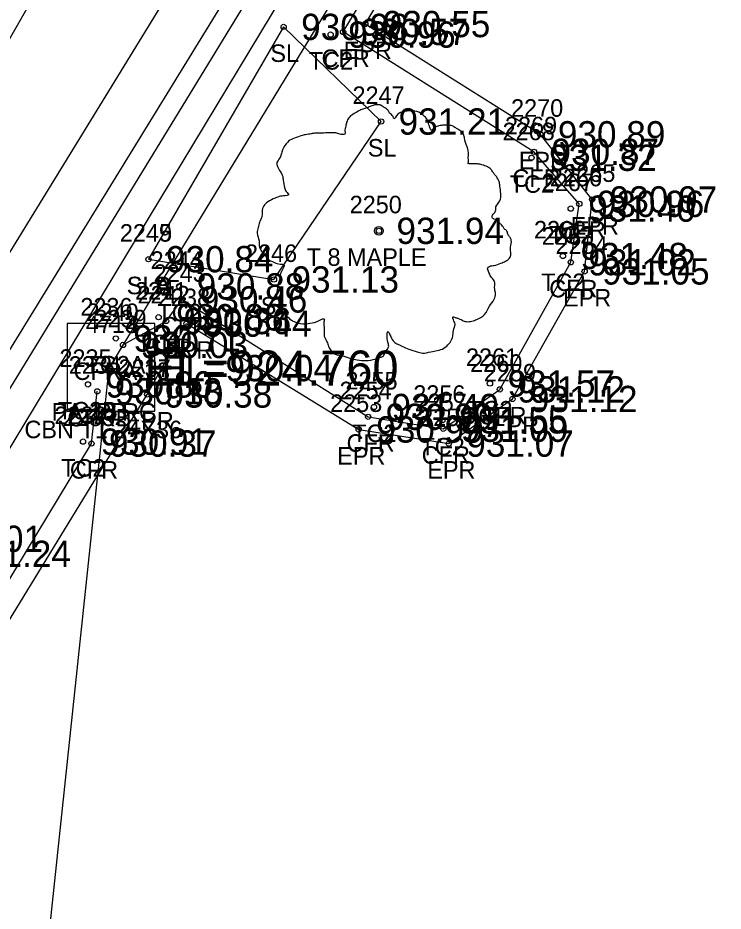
# Model space of a CAD drawing. Extents: x 1575382 to 1578175, y 1099175 to 1101955.
# Drawn here: x 1576685.7 to 1576726, y 1099948.9 to 1099999.9 of the extents above; entities that cross this region are included whole.
import ezdxf

# ---------------------------------------------------------------- set-up
doc = ezdxf.new("R2010")
doc.units = 0
for name, color, linetype in [('RD_EX_BldgApp', 7, 'Continuous'), ('RD_EX_Conc', 7, 'Continuous'), ('RD_EX_Conc_txCode', 7, 'Continuous'), ('RD_EX_DR_Inlet', 7, 'Continuous'), ('RD_EX_DR_Inlet_txCode', 7, 'Continuous'), ('RD_EX_DR_Pipe', 7, 'Continuous'), ('RD_EX_DR_Pipe_txCode', 7, 'Continuous'), ('RD_EX_Fence_Other', 7, 'Continuous'), ('RD_EX_Misc', 7, 'Continuous'), ('RD_EX_Road', 7, 'Continuous'), ('RD_EX_Road_txCode', 7, 'Continuous'), ('RD_EX_TX_Conc_ELEV', 7, 'Continuous'), ('RD_EX_TX_DR_Inlet_ELEV', 7, 'Continuous'), ('RD_EX_TX_Misc_ELEV', 7, 'Continuous'), ('RD_EX_TX_Road_ELEV', 7, 'Continuous'), ('RD_EX_TX_VEG_ELEV', 7, 'Continuous'), ('RD_EX_VEG', 7, 'Continuous'), ('RD_EX_VEG_txCode', 7, 'Continuous'), ('RD_SMD_Locator', 7, 'Continuous'), ('RD_TX_Pipe_ElevEX', 7, 'Continuous')]:
    doc.layers.add(name, color=color, linetype=linetype)

msp = doc.modelspace()

# ---------------------------------------------------------------- linework, layer by layer
at = {"layer": 'RD_EX_BldgApp'}
msp.add_lwpolyline([(1576672.285, 1099877.607), (1576646.299, 1099893.421), (1576642.266, 1099901.79), (1576647.555, 1099912.985), (1576656.827, 1099928.617), (1576681.633, 1099969.334), (1576707.301, 1100011.852), (1576732.079, 1100052.807), (1576750.28, 1100082.51)], dxfattribs=at)
at = {"layer": 'RD_EX_Conc'}
for points in [[(1576611.554, 1099868.428), (1576613.247, 1099872.406), (1576617.21, 1099879.286), (1576621.441, 1099887.05), (1576646.337, 1099930.819), (1576671.483, 1099974.604), (1576671.483, 1099974.604), (1576695.542, 1100016.682), (1576720.221, 1100060.326), (1576739.554, 1100094.658), (1576745.882, 1100101.997), (1576748.748, 1100106.27)], [(1576691.742, 1099981.252), (1576694.204, 1099982.615), (1576695.12, 1099983.846), (1576705.726, 1099977.153), (1576710.014, 1099976.47), (1576713.243, 1099978.715), (1576717.287, 1099985.965), (1576717.771, 1099989.301), (1576715.187, 1099992.268), (1576704.298, 1099999.106), (1576727.807, 1100037.817), (1576755.44, 1100083.606), (1576755.816, 1100086.63)], [(1576682.917, 1099888.226), (1576664.939, 1099899.246), (1576666.414, 1099902.476), (1576666.207, 1099905.232), (1576663.825, 1099907.894), (1576652.51, 1099913.643), (1576689.941, 1099975.624), (1576690.276, 1099978.605)]]:
    msp.add_lwpolyline(points, dxfattribs=at)
at = {"layer": 'RD_EX_DR_Inlet'}
msp.add_line((1576693.553, 1099977.474), (1576693.553, 1099982.475), dxfattribs=at)
msp.add_lwpolyline([(1576693.553, 1099977.474), (1576693.553, 1099982.475), (1576688.553, 1099982.475), (1576688.553, 1099977.474)], close=True, dxfattribs=at)
at = {"layer": 'RD_EX_DR_Pipe'}
msp.add_lwpolyline([(1576678.585, 1099863.473), (1576690.962, 1099979.929), (1576690.962, 1099979.929), (1576756.712, 1100087.957)], dxfattribs=at)
at = {"layer": 'RD_EX_Fence_Other'}
msp.add_lwpolyline([(1576679.251, 1099869.09), (1576645.16, 1099889.942), (1576639.542, 1099895.597), (1576638.955, 1099903.536), (1576642.17, 1099910.834), (1576742.455, 1100074.012)], dxfattribs=at)
at = {"layer": 'RD_EX_Misc'}
msp.add_lwpolyline([(1576682.856, 1099868.559), (1576662.275, 1099880.956), (1576644.684, 1099891.532), (1576640.031, 1099896.906), (1576640.013, 1099902.654), (1576645.377, 1099914.364), (1576654.842, 1099929.018), (1576680.046, 1099970.191), (1576705.641, 1100012.054), (1576731.304, 1100053.647), (1576749.148, 1100082.966)], dxfattribs=at)
at = {"layer": 'RD_EX_Road'}
msp.add_lwpolyline([(1576683.421, 1099888.983), (1576666.056, 1099899.537), (1576667.205, 1099902.209), (1576666.936, 1099905.875), (1576664.417, 1099908.527), (1576653.805, 1099914.11), (1576693.118, 1099978.425), (1576695.365, 1099982.465), (1576705.188, 1099976.428), (1576710.327, 1099975.622), (1576713.96, 1099978.167), (1576718.075, 1099985.444), (1576718.509, 1099989.55), (1576715.55, 1099993.268), (1576705.563, 1099999.558), (1576728.513, 1100037.374), (1576758.647, 1100086.731), (1576760.699, 1100090.217), (1576769.982, 1100084.647), (1576773.314, 1100083.71), (1576776.467, 1100084.773), (1576777.624, 1100085.825)], dxfattribs=at)
at = {"layer": 'RD_EX_VEG'}
for points in [[(1576677.215, 1099867.172), (1576638.056, 1099891.643), (1576635.862, 1099906.003), (1576755.277, 1100100.621), (1576767.632, 1100094.218)], [(1576693.193, 1099986.142), (1576700.355, 1099984.984), (1576706.465, 1099993.997), (1576700.906, 1099999.395), (1576693.193, 1099986.142)]]:
    msp.add_lwpolyline(points, dxfattribs=at)
for centre, radius in [((1576706.342, 1099987.761), 0.25), ((1576706.33, 1099987.742), 0.0001)]:
    msp.add_circle(centre, radius, dxfattribs=at)
for points in [[(1576706.474, 1099994.929), (1576706.174, 1099994.954), (1576705.849, 1099994.854), (1576705.6, 1099994.754), (1576705.375, 1099994.679), (1576705.15, 1099994.579), (1576704.85, 1099994.404), (1576704.625, 1099994.204), (1576704.5, 1099993.954), (1576704.45, 1099993.729), (1576704.4, 1099993.454), (1576704.4, 1099993.279), (1576704.275, 1099993.254), (1576704.125, 1099993.279), (1576703.875, 1099993.354), (1576703.625, 1099993.354), (1576703.375, 1099993.354), (1576703.026, 1099993.329), (1576702.676, 1099993.329), (1576702.401, 1099993.279), (1576702.076, 1099993.229), (1576701.701, 1099993.104), (1576701.351, 1099992.979), (1576701.052, 1099992.729), (1576700.802, 1099992.255), (1576700.677, 1099991.905), (1576700.527, 1099991.655), (1576700.677, 1099991.205), (1576700.852, 1099990.855), (1576700.877, 1099990.655), (1576700.952, 1099990.231), (1576701.052, 1099990.006), (1576701.176, 1099989.806), (1576701.102, 1099989.781), (1576700.727, 1099989.731), (1576700.427, 1099989.631), (1576700.002, 1099989.406), (1576699.777, 1099989.181), (1576699.677, 1099988.856), (1576699.652, 1099988.506), (1576699.552, 1099988.306), (1576699.477, 1099988.032), (1576699.452, 1099987.957), (1576699.402, 1099987.632), (1576699.502, 1099987.182), (1576699.527, 1099986.832), (1576699.652, 1099986.607), (1576699.802, 1099986.432), (1576699.977, 1099986.182), (1576700.377, 1099985.957), (1576700.702, 1099985.857), (1576700.902, 1099985.833), (1576700.727, 1099985.333), (1576700.677, 1099984.983), (1576700.552, 1099984.583), (1576700.552, 1099984.508), (1576700.502, 1099984.033), (1576700.652, 1099983.708), (1576700.727, 1099983.334), (1576700.902, 1099983.109), (1576701.176, 1099982.809), (1576701.501, 1099982.584), (1576702.001, 1099982.459), (1576702.401, 1099982.484), (1576702.976, 1099982.659), (1576703.226, 1099982.734), (1576703.201, 1099982.559), (1576703.226, 1099982.184), (1576703.226, 1099981.759), (1576703.375, 1099981.434), (1576703.475, 1099981.16), (1576703.625, 1099980.91), (1576703.95, 1099980.685), (1576704.35, 1099980.61), (1576704.775, 1099980.46), (1576705.225, 1099980.385), (1576705.724, 1099980.36), (1576706.324, 1099980.51), (1576706.599, 1099980.635), (1576706.699, 1099980.81), (1576706.899, 1099981.185), (1576706.849, 1099981.409), (1576706.874, 1099982.009), (1576706.974, 1099981.834), (1576707.149, 1099981.484), (1576707.649, 1099981.185), (1576708.048, 1099981.01), (1576708.523, 1099980.86), (1576708.823, 1099980.785), (1576709.298, 1099980.86), (1576709.673, 1099980.935), (1576710.048, 1099981.06), (1576710.347, 1099981.334), (1576710.522, 1099981.609), (1576710.572, 1099981.884), (1576710.647, 1099982.259), (1576710.697, 1099982.434)], [(1576710.697, 1099982.434), (1576710.622, 1099982.609), (1576710.572, 1099982.859), (1576710.647, 1099982.834), (1576710.822, 1099982.784), (1576711.097, 1099982.659), (1576711.322, 1099982.584), (1576711.647, 1099982.609), (1576711.922, 1099982.709), (1576712.372, 1099982.984), (1576712.646, 1099983.459), (1576712.921, 1099983.858), (1576712.996, 1099984.183), (1576712.946, 1099984.408), (1576712.921, 1099984.908), (1576712.721, 1099985.158), (1576712.671, 1099985.283), (1576712.571, 1099985.683), (1576712.646, 1099985.733), (1576712.921, 1099985.783), (1576713.296, 1099985.907), (1576713.571, 1099986.032), (1576713.796, 1099986.207), (1576713.871, 1099986.432), (1576713.846, 1099986.832), (1576713.896, 1099987.232), (1576713.821, 1099987.382), (1576713.721, 1099987.532), (1576713.646, 1099987.732), (1576713.496, 1099987.882), (1576713.396, 1099988.032), (1576713.296, 1099988.131), (1576713.171, 1099988.281), (1576712.996, 1099988.406), (1576712.846, 1099988.456), (1576712.796, 1099988.606), (1576712.946, 1099988.806), (1576712.996, 1099988.906), (1576713.021, 1099989.131), (1576713.246, 1099989.481), (1576713.296, 1099989.881), (1576713.246, 1099990.306), (1576713.196, 1099990.58), (1576713.046, 1099990.855), (1576712.846, 1099991.105), (1576712.721, 1099991.28), (1576712.546, 1099991.405), (1576712.222, 1099991.53), (1576711.972, 1099991.58), (1576711.622, 1099991.58), (1576711.422, 1099991.63), (1576711.447, 1099991.68), (1576711.447, 1099991.83), (1576711.447, 1099992.105), (1576711.372, 1099992.555), (1576711.222, 1099993.054), (1576711.222, 1099993.079), (1576711.122, 1099993.329), (1576710.897, 1099993.529), (1576710.722, 1099993.629), (1576710.522, 1099993.754), (1576710.272, 1099993.779), (1576709.973, 1099993.779), (1576709.698, 1099993.729), (1576709.498, 1099993.629), (1576709.323, 1099993.504), (1576709.248, 1099993.654), (1576709.148, 1099993.954), (1576709.098, 1099994.104), (1576708.948, 1099994.279), (1576708.723, 1099994.479), (1576708.273, 1099994.604), (1576707.649, 1099994.529), (1576707.349, 1099994.329), (1576707.199, 1099994.154), (1576707.149, 1099994.279), (1576706.949, 1099994.479), (1576706.849, 1099994.654), (1576706.674, 1099994.779), (1576706.524, 1099994.879), (1576706.424, 1099994.929)]]:
    msp.add_spline(points, degree=3, dxfattribs=at)
at = {"layer": 'RD_SMD_Locator'}
for centre, radius in [((1576700.906, 1099999.395), 0.15), ((1576705.563, 1099999.558), 0.15), ((1576703.588, 1099998.956), 0.15), ((1576704.298, 1099999.106), 0.15), ((1576706.465, 1099993.997), 0.15), ((1576715.55, 1099993.268), 0.15), ((1576715.187, 1099992.268), 0.15), ((1576715.049, 1099991.929), 0.15), ((1576718.509, 1099989.55), 0.15), ((1576717.285, 1099989.027), 0.15), ((1576717.771, 1099989.301), 0.15), ((1576706.342, 1099987.761), 0.15), ((1576693.193, 1099986.142), 0.15), ((1576693.193, 1099986.142), 0.15), ((1576716.84, 1099986.324), 0.15), ((1576717.287, 1099985.965), 0.15), ((1576700.355, 1099984.984), 0.15), ((1576718.075, 1099985.444), 0.15), ((1576694.948, 1099984.59), 0.15), ((1576695.12, 1099983.846), 0.15), ((1576693.774, 1099982.832), 0.15), ((1576694.204, 1099982.615), 0.15), ((1576695.365, 1099982.465), 0.15), ((1576691.33, 1099981.62), 0.15), ((1576691.742, 1099981.252), 0.15), ((1576690.962, 1099979.929), 0.2), ((1576690.962, 1099979.929), 0.2), ((1576690.962, 1099979.929), 0.15), ((1576689.744, 1099978.998), 0.15), ((1576712.676, 1099979.052), 0.15), ((1576690.276, 1099978.605), 0.15), ((1576693.118, 1099978.425), 0.15), ((1576713.243, 1099978.715), 0.15), ((1576713.96, 1099978.167), 0.15), ((1576706.062, 1099977.711), 0.15), ((1576705.726, 1099977.153), 0.15), ((1576709.955, 1099976.948), 0.15), ((1576705.188, 1099976.428), 0.15), ((1576710.014, 1099976.47), 0.15), ((1576689.462, 1099975.735), 0.15), ((1576689.941, 1099975.624), 0.15), ((1576710.327, 1099975.622), 0.15)]:
    msp.add_circle(centre, radius, dxfattribs=at)

# ---------------------------------------------------------------- texts
at = {"layer": 'RD_EX_Conc_txCode'}
for s, p in [('TC2', (1576702.344, 1099996.956)), ('CFR', (1576703.069, 1099997.106)), ('2269', (1576713.533, 1099993.268)), ('2268', (1576713.396, 1099992.929)), ('CFR', (1576713.958, 1099990.268)), ('2266', (1576716.094, 1099990.301)), ('TC2', (1576713.805, 1099989.929)), ('2267', (1576715.631, 1099990.027)), ('2262', (1576715.187, 1099987.324)), ('CFR', (1576716.542, 1099987.301)), ('2263', (1576715.633, 1099986.965)), ('TC2', (1576716.041, 1099987.027)), ('2244', (1576693.318, 1099985.59)), ('2243', (1576693.49, 1099984.846)), ('TC2', (1576715.596, 1099984.324)), ('2241', (1576692.427, 1099983.832)), ('2242', (1576692.574, 1099983.615)), ('CFR', (1576716.058, 1099983.965)), ('2240', (1576689.66, 1099982.62)), ('TC2', (1576693.704, 1099982.59)), ('2239', (1576690.112, 1099982.252)), ('CFR', (1576693.891, 1099981.846)), ('TC2', (1576692.53, 1099980.832)), ('CFR', (1576692.976, 1099980.615)), ('2261', (1576711.306, 1099980.052)), ('2235', (1576688.114, 1099979.998)), ('2234', (1576688.646, 1099979.605)), ('TC2A', (1576689.597, 1099979.62)), ('2260', (1576711.55, 1099979.715)), ('CFRA 18', (1576688.923, 1099979.252)), ('2255', (1576704.432, 1099978.711)), ('2254', (1576704.096, 1099978.153)), ('2256', (1576708.301, 1099977.948)), ('2257', (1576708.384, 1099977.47)), ('TC2B', (1576688.027, 1099976.998)), ('TC2', (1576711.432, 1099977.052)), ('2232', (1576687.832, 1099976.735)), ('2233', (1576688.311, 1099976.624)), ('CFRB', (1576688.576, 1099976.605)), ('CFR', (1576712.015, 1099976.715)), ('TC2', (1576704.817, 1099975.711)), ('CFR', (1576704.498, 1099975.153)), ('TC2', (1576708.711, 1099974.948)), ('CFR', (1576708.785, 1099974.47)), ('TC2', (1576688.218, 1099973.735)), ('CFR', (1576688.713, 1099973.624))]:
    msp.add_text(s, height=1, dxfattribs=at).set_placement(p)
at = {"layer": 'RD_EX_DR_Inlet_txCode'}
for s, p in [('2236', (1576689.308, 1099982.929)), ('CBN T1 24X36', (1576686.119, 1099975.929))]:
    msp.add_text(s, height=1, dxfattribs=at).set_placement(p)
at = {"layer": 'RD_EX_DR_Pipe_txCode'}
for s, p in [('4713', (1576689.616, 1099981.929)), ('4714', (1576689.616, 1099981.929)), ('PA 18 RC', (1576687.671, 1099976.929)), ('PB', (1576690.182, 1099976.929))]:
    msp.add_text(s, height=1, dxfattribs=at).set_placement(p)
at = {"layer": 'RD_EX_Road_txCode'}
for s, p in [('EPR', (1576704.334, 1099997.558)), ('2270', (1576713.88, 1099994.268)), ('EPR', (1576714.321, 1099991.268)), ('2265', (1576716.855, 1099990.55)), ('EPR', (1576717.281, 1099987.55)), ('2264', (1576716.421, 1099986.444)), ('2238', (1576693.735, 1099983.465)), ('EPR', (1576716.847, 1099983.444)), ('EPR', (1576694.137, 1099980.465)), ('2237', (1576691.488, 1099979.425)), ('2259', (1576712.33, 1099979.167)), ('2253', (1576703.558, 1099977.428)), ('2258', (1576708.697, 1099976.622)), ('EPR', (1576691.89, 1099976.425)), ('EPR', (1576712.731, 1099976.167)), ('EPR', (1576703.959, 1099974.428)), ('EPR', (1576709.099, 1099973.622))]:
    msp.add_text(s, height=1, dxfattribs=at).set_placement(p)
at = {"layer": 'RD_EX_TX_Conc_ELEV'}
for s, p in [('930.57', (1576705.298, 1099998.356)), ('930.96', (1576704.588, 1099998.206)), ('930.87', (1576716.187, 1099991.518)), ('931.32', (1576716.049, 1099991.179)), ('931.40', (1576718.285, 1099988.277)), ('930.96', (1576718.771, 1099988.551)), ('931.48', (1576717.84, 1099985.574)), ('931.02', (1576718.287, 1099985.215)), ('930.88', (1576695.948, 1099983.84)), ('930.46', (1576696.12, 1099983.096)), ('930.88', (1576694.774, 1099982.082)), ('930.36', (1576695.204, 1099981.865)), ('930.71', (1576692.33, 1099980.87)), ('930.03', (1576692.742, 1099980.502)), ('930.80', (1576690.744, 1099978.248)), ('931.57', (1576713.676, 1099978.302)), ('931.12', (1576714.243, 1099977.965)), ('930.13', (1576691.276, 1099977.855)), ('931.49', (1576707.062, 1099976.961)), ('930.99', (1576706.726, 1099976.403)), ('931.55', (1576710.955, 1099976.198)), ('931.09', (1576711.014, 1099975.72)), ('930.91', (1576690.462, 1099974.985)), ('930.37', (1576690.941, 1099974.874))]:
    msp.add_text(s, height=1.5, dxfattribs=at).set_placement(p)
at = {"layer": 'RD_EX_TX_DR_Inlet_ELEV'}
msp.add_text('EL=930.04', height=1.5, dxfattribs=at).set_placement((1576693.962, 1099979.179))
at = {"layer": 'RD_EX_TX_Misc_ELEV'}
for s, p in [('940.01', (1576681.046, 1099969.441)), ('931.24', (1576682.633, 1099968.584))]:
    msp.add_text(s, height=1.5, dxfattribs=at).set_placement(p)
at = {"layer": 'RD_EX_TX_Road_ELEV'}
for s, p in [('930.55', (1576706.563, 1099998.808)), ('930.89', (1576716.55, 1099992.518)), ('930.97', (1576719.509, 1099988.8)), ('931.05', (1576719.075, 1099984.694)), ('930.44', (1576696.365, 1099981.715)), ('930.38', (1576694.118, 1099977.675)), ('931.12', (1576714.96, 1099977.417)), ('930.99', (1576706.188, 1099975.678)), ('931.07', (1576711.327, 1099974.872))]:
    msp.add_text(s, height=1.5, dxfattribs=at).set_placement(p)
at = {"layer": 'RD_EX_TX_VEG_ELEV'}
for s, p in [('930.98', (1576701.906, 1099998.645)), ('931.21', (1576707.465, 1099993.247)), ('931.94', (1576707.342, 1099987.011)), ('930.84', (1576694.193, 1099985.392)), ('930.84', (1576694.193, 1099985.392)), ('931.13', (1576701.355, 1099984.234))]:
    msp.add_text(s, height=1.5, dxfattribs=at).set_placement(p)
at = {"layer": 'RD_EX_VEG_txCode'}
for s, p in [('SL', (1576700.15, 1099997.395)), ('2247', (1576704.835, 1099994.997)), ('SL', (1576705.709, 1099991.997)), ('2250', (1576704.673, 1099988.761)), ('2245', (1576691.563, 1099987.142)), ('2249', (1576691.563, 1099987.142)), ('2246', (1576698.701, 1099985.984)), ('T 8 MAPLE', (1576702.22, 1099985.761)), ('SLA', (1576691.949, 1099984.142)), ('SLB', (1576691.965, 1099984.142)), ('SL', (1576699.599, 1099982.984))]:
    msp.add_text(s, height=1, dxfattribs=at).set_placement(p)
at = {"layer": 'RD_TX_Pipe_ElevEX'}
msp.add_text('EL=924.760', height=2, dxfattribs=at).set_placement((1576692.962, 1099978.929))
msp.add_text('EL=924.760', height=2, dxfattribs=at).set_placement((1576692.962, 1099978.929))

doc.saveas('drawing.dxf')
